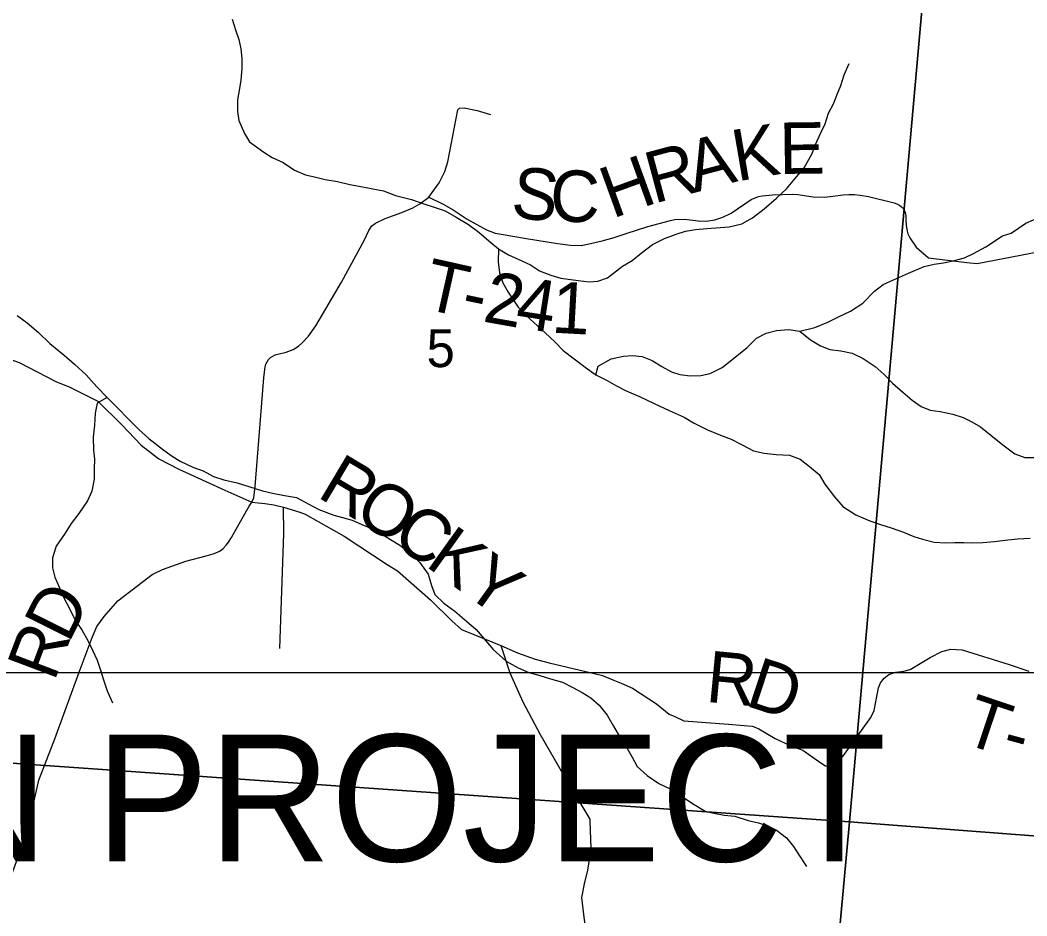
# Model space of a CAD drawing. Extents: x 0 to 34, y 0 to 22.
# Drawn here: x 6.672 to 7.784, y 17.231 to 18.22 of the extents above; entities that cross this region are included whole.
import ezdxf

# ---------------------------------------------------------------- set-up
doc = ezdxf.new("R2010")
doc.units = 0
for name, color, linetype in [('GM_X_Corporation', 7, 'Continuous'), ('GM_X_County_Road', 7, 'Continuous'), ('GM_X_County_Road_Text', 7, 'Continuous'), ('GM_X_Minor_River', 7, 'Continuous'), ('GM_X_Section_Text', 7, 'Continuous'), ('GM_X_Township_Road', 7, 'Continuous'), ('GM_X_Township_Road_Text', 7, 'Continuous'), ('SH_Data', 7, 'Continuous'), ('SH_Text', 7, 'Continuous')]:
    doc.layers.add(name, color=color, linetype=linetype)

msp = doc.modelspace()

# ---------------------------------------------------------------- linework, layer by layer
at = {"layer": 'GM_X_Corporation'}
for points in [[(6.6744, 18.4075), (7.6778, 18.3345), (7.5885, 17.3345), (6.5737, 17.4057)], [(7.6778, 18.3345), (8.6957, 18.2606), (8.5882, 17.2585), (7.5885, 17.3345)], [(6.5737, 17.4057), (7.5885, 17.3345), (7.4964, 16.3324), (6.463, 16.4089)], [(7.5885, 17.3345), (8.5882, 17.2585), (8.4813, 16.2644), (7.4964, 16.3324)]]:
    msp.add_lwpolyline(points, close=True, dxfattribs=at)
at = {"layer": 'GM_X_County_Road'}
msp.add_line((6.7375, 17.4998), (6.7375, 17.4998), dxfattribs=at)
for points in [[(6.2118, 17.9588), (6.2321, 17.9588), (6.2643, 17.95), (6.3295, 17.9354), (6.4064, 17.9208), (6.4599, 17.9101), (6.4852, 17.9043), (6.5222, 17.8926), (6.6078, 17.8644), (6.6711, 17.842), (6.7117, 17.8211), (6.7272, 17.8149), (6.7579, 17.7992), (6.7847, 17.773), (6.8061, 17.7506), (6.8254, 17.7355), (6.8475, 17.7243), (6.8983, 17.7008), (6.9283, 17.6876)], [(6.6455, 17.2305), (6.6736, 17.3056), (6.6834, 17.3382), (6.6929, 17.3807), (6.7105, 17.4262), (6.7375, 17.4998), (6.7519, 17.5381), (6.757, 17.5502), (6.7651, 17.5615), (6.7801, 17.5789), (6.818, 17.6079), (6.8295, 17.6135), (6.8554, 17.6224), (6.8779, 17.6283), (6.8856, 17.6306), (6.8903, 17.6324), (6.8933, 17.634), (6.8966, 17.6365), (6.9, 17.6401), (6.9026, 17.6437), (6.9056, 17.6488), (6.9176, 17.6697), (6.9253, 17.6832), (6.9283, 17.6876)]]:
    msp.add_lwpolyline(points, dxfattribs=at)
at = {"layer": 'GM_X_Minor_River'}
for p, q in [((6.7607, 17.5033), (6.762, 17.4995)), ((7.2226, 17.5048), (7.2343, 17.4995)), ((7.2343, 17.4995), (7.2343, 17.4995))]:
    msp.add_line(p, q, dxfattribs=at)
for points in [[(6.9066, 18.2213), (6.91, 18.2095), (6.9138, 18.1989), (6.9161, 18.1886), (6.9172, 18.178), (6.9172, 18.1666), (6.916, 18.154), (6.9145, 18.1445), (6.9122, 18.132), (6.9122, 18.1191), (6.9137, 18.1092), (6.9201, 18.0951), (6.9258, 18.0856), (6.9413, 18.0742), (6.9508, 18.0685), (6.963, 18.0631), (6.9755, 18.0544), (6.9876, 18.0494), (6.999, 18.0467), (7.0093, 18.0441), (7.0229, 18.0418), (7.0366, 18.0387), (7.0469, 18.0368), (7.0601, 18.0341), (7.0738, 18.0318), (7.0871, 18.0264), (7.1046, 18.0222), (7.1182, 18.0173), (7.1296, 18.0135), (7.1418, 18.0096), (7.1539, 18.0024), (7.1676, 17.9944), (7.1789, 17.986), (7.1899, 17.9765), (7.2006, 17.9674), (7.2119, 17.9609), (7.2264, 17.9544), (7.2359, 17.9498), (7.2461, 17.9433), (7.2586, 17.9384), (7.2696, 17.9353), (7.2886, 17.9326), (7.3012, 17.9311), (7.3106, 17.9318), (7.3213, 17.9356), (7.3376, 17.9485), (7.3483, 17.9546), (7.3582, 17.9629), (7.3707, 17.9724), (7.384, 17.9788), (7.3969, 17.9838), (7.4072, 17.9872), (7.4182, 17.989), (7.4308, 17.9902), (7.441, 17.9909), (7.4555, 17.992), (7.4695, 17.995), (7.4813, 18.0019), (7.4942, 18.0117), (7.5079, 18.0235), (7.519, 18.0337), (7.53, 18.047), (7.5384, 18.0569), (7.5471, 18.0728), (7.5509, 18.0827), (7.557, 18.0956), (7.5616, 18.1058), (7.5654, 18.1176), (7.5708, 18.1279)], [(7.5708, 18.1279), (7.5746, 18.1374), (7.5788, 18.148), (7.5826, 18.1598), (7.5883, 18.1723)], [(7.3082, 17.8285), (7.3109, 17.838), (7.3253, 17.8459), (7.339, 17.8489), (7.3489, 17.8497), (7.3595, 17.8485), (7.3705, 17.8443), (7.3811, 17.8375), (7.3918, 17.8318), (7.4012, 17.8287), (7.4126, 17.8272), (7.4244, 17.8275), (7.4347, 17.8298), (7.448, 17.8366), (7.4605, 17.8465), (7.4754, 17.8586), (7.4856, 17.8688), (7.4963, 17.8745), (7.5077, 17.8775), (7.5213, 17.8783), (7.5335, 17.8767), (7.5502, 17.8805), (7.5647, 17.8866), (7.5764, 17.8926), (7.5897, 17.8987), (7.6031, 17.9074), (7.616, 17.9207), (7.6259, 17.9283), (7.6373, 17.9332), (7.6536, 17.9408), (7.6711, 17.948), (7.6821, 17.9506), (7.6924, 17.9521), (7.703, 17.9544), (7.7156, 17.9578), (7.7254, 17.9623), (7.7391, 17.9699), (7.7574, 17.982), (7.7673, 17.985), (7.7832, 17.996), (7.8003, 18.0032)], [(7.2006, 17.9674), (7.2002, 17.9533), (7.202, 17.9411), (7.2054, 17.9301), (7.2115, 17.9198), (7.2225, 17.9031), (7.2358, 17.8898), (7.2521, 17.8753), (7.2634, 17.8646), (7.2722, 17.8551), (7.2964, 17.8369), (7.3082, 17.8285), (7.3207, 17.822), (7.331, 17.8163), (7.3416, 17.8106), (7.3564, 17.8045), (7.3727, 17.7968), (7.3894, 17.7888), (7.4057, 17.7816), (7.4163, 17.7755), (7.4315, 17.7678), (7.4459, 17.7617), (7.4577, 17.7572), (7.4691, 17.7514), (7.4824, 17.7446), (7.4942, 17.7419), (7.5074, 17.7404), (7.5223, 17.7396), (7.534, 17.7354), (7.5443, 17.727), (7.5549, 17.7182), (7.5613, 17.7076), (7.5719, 17.6935), (7.581, 17.6829), (7.5954, 17.6737), (7.611, 17.6672), (7.6228, 17.663), (7.6345, 17.6592), (7.6482, 17.6546), (7.6596, 17.6497), (7.6691, 17.647), (7.682, 17.6435), (7.6949, 17.6428), (7.7048, 17.6431), (7.7147, 17.6431), (7.7249, 17.6427), (7.7359, 17.6431), (7.7488, 17.6442), (7.7633, 17.6461), (7.7743, 17.6472), (7.7883, 17.6479)], [(6.6691, 17.8938), (6.6801, 17.8858), (6.6926, 17.8751), (6.7051, 17.8629), (6.7207, 17.85), (6.7324, 17.8401), (6.7453, 17.8283), (6.7571, 17.815), (6.7684, 17.8032), (6.8033, 17.7681), (6.8143, 17.7582), (6.8295, 17.7461), (6.839, 17.7392), (6.8492, 17.7331), (6.8629, 17.7262), (6.8743, 17.7224), (6.886, 17.7159), (6.8974, 17.7125), (6.9119, 17.7091), (6.9248, 17.7052), (6.9399, 17.7003), (6.951, 17.6976), (6.9642, 17.6949), (6.9775, 17.693), (6.9912, 17.6854), (7.0022, 17.6796), (7.0189, 17.6735), (7.0284, 17.6709), (7.039, 17.6678), (7.0496, 17.6632), (7.0603, 17.6586), (7.072, 17.6525), (7.0815, 17.6464), (7.0918, 17.6403), (7.1047, 17.6308), (7.1134, 17.6213), (7.1229, 17.608), (7.1266, 17.5958), (7.1304, 17.5856), (7.1403, 17.576), (7.1524, 17.5673), (7.1653, 17.5562), (7.1759, 17.5471), (7.1846, 17.5372), (7.1949, 17.525), (7.2093, 17.5121), (7.2226, 17.5048), (7.2343, 17.4995), (7.2465, 17.4964), (7.2583, 17.4926), (7.2715, 17.4888), (7.2829, 17.4831), (7.2932, 17.4774), (7.3027, 17.4717), (7.3121, 17.4633), (7.3209, 17.4526), (7.3277, 17.4404)], [(7.5335, 17.8767), (7.5453, 17.8672), (7.5563, 17.8604), (7.5669, 17.8565), (7.579, 17.855), (7.5916, 17.8523), (7.6037, 17.8466), (7.617, 17.8375), (7.6269, 17.8287), (7.6359, 17.8192), (7.6473, 17.8093), (7.6576, 17.8005), (7.6678, 17.7933), (7.6777, 17.7895), (7.6887, 17.7879), (7.7027, 17.7849), (7.7141, 17.7811), (7.7236, 17.7765), (7.7331, 17.7711), (7.7445, 17.7616), (7.7578, 17.751), (7.771, 17.7411), (7.7824, 17.7372), (7.7965, 17.7372)], [(6.7684, 17.8032), (6.7574, 17.7971), (6.7551, 17.7861), (6.7543, 17.7728), (6.7528, 17.7595), (6.7532, 17.745), (6.7543, 17.7352), (6.7539, 17.7245), (6.7539, 17.7131), (6.7516, 17.6998), (6.7466, 17.6892), (6.7371, 17.6752), (6.7287, 17.6641), (6.7219, 17.6535), (6.712, 17.6391), (6.7078, 17.6262), (6.7081, 17.6152), (6.7104, 17.6049), (6.721, 17.5813), (6.7267, 17.5703), (6.7335, 17.5566), (6.7403, 17.5467), (6.7475, 17.5342), (6.7524, 17.5235), (6.7573, 17.5132), (6.7607, 17.5033), (6.7641, 17.4927), (6.7683, 17.4794), (6.7743, 17.4661)], [(7.3277, 17.4404), (7.3345, 17.429), (7.3409, 17.4188), (7.3485, 17.4062), (7.3538, 17.3956), (7.3648, 17.3857), (7.3777, 17.3769), (7.391, 17.3708), (7.405, 17.3613), (7.4168, 17.3537), (7.4289, 17.3464), (7.4388, 17.3441), (7.4502, 17.3418), (7.462, 17.3407), (7.4764, 17.3361), (7.4878, 17.3334), (7.498, 17.33), (7.5079, 17.3254), (7.5189, 17.317), (7.5268, 17.3075), (7.5325, 17.298), (7.5409, 17.2851)]]:
    msp.add_lwpolyline(points, dxfattribs=at)
at = {"layer": 'GM_X_Township_Road'}
for p, q in [((7.2134, 17.4991), (7.2134, 17.4991)), ((7.2972, 17.5007), (7.3021, 17.4995)), ((7.6383, 17.4995), (7.6398, 17.5)), ((7.6398, 17.5), (7.6486, 17.5009)), ((7.6486, 17.5009), (7.6555, 17.5027))]:
    msp.add_line(p, q, dxfattribs=at)
for points in [[(7.1238, 18.0248), (7.1294, 18.0325), (7.1352, 18.0406), (7.1379, 18.0456), (7.1414, 18.0531), (7.1448, 18.0638), (7.1557, 18.1211), (7.1576, 18.1229), (7.1629, 18.1232), (7.177, 18.1204), (7.1919, 18.1159)], [(7.6652, 17.9667), (7.6759, 17.9575), (7.6789, 17.9572), (7.7183, 17.9525), (7.7297, 17.9515), (7.8943, 17.983), (7.9266, 17.9983), (7.948, 18.0062), (8.0137, 18.0356), (8.0309, 18.0433), (8.0483, 18.0551), (8.0653, 18.0717)], [(6.9283, 17.6876), (6.9304, 17.6926), (6.9318, 17.7051), (6.9414, 17.825), (6.9428, 17.8371), (6.9437, 17.84), (6.9467, 17.8453), (6.9487, 17.8474), (6.9539, 17.8503), (6.9568, 17.8513), (6.966, 17.8535), (6.974, 17.8564), (6.9797, 17.86), (6.9843, 17.864), (6.9907, 17.871), (6.9989, 17.8824), (7.0272, 17.9306), (7.0527, 17.9775), (7.0574, 17.9878), (7.0609, 17.9928), (7.065, 17.996), (7.0755, 18.001), (7.094, 18.0076), (7.1062, 18.0127), (7.1137, 18.0172), (7.1238, 18.0248), (7.1395, 18.0168), (7.1505, 18.0108), (7.1661, 18.0005), (7.1876, 17.9884), (7.1969, 17.985), (7.2036, 17.9836), (7.2316, 17.979), (7.2659, 17.9735), (7.2801, 17.9717), (7.2924, 17.9714), (7.3152, 17.9763), (7.3287, 17.98), (7.3419, 17.9846), (7.3657, 17.9921), (7.3906, 17.999), (7.3956, 18.0001), (7.4063, 18.0002), (7.4213, 17.9986), (7.4305, 17.9983), (7.4397, 17.9997), (7.4487, 18.0024), (7.4577, 18.0068), (7.4797, 18.0219), (7.4878, 18.0252), (7.4922, 18.0262), (7.5036, 18.0273), (7.5258, 18.0281), (7.5314, 18.0277), (7.5484, 18.0251), (7.5608, 18.0248), (7.57, 18.0258), (7.5817, 18.0272), (7.5878, 18.0276), (7.594, 18.0276), (7.6002, 18.027), (7.6095, 18.0254), (7.6378, 18.0182), (7.6408, 18.0174), (7.6437, 18.0159), (7.6459, 18.0141), (7.6478, 18.0122), (7.649, 18.0101), (7.65, 18.0077), (7.6506, 18.0041), (7.6509, 17.9997), (7.6513, 17.9933), (7.6522, 17.987), (7.6531, 17.9841), (7.6543, 17.9812), (7.656, 17.9786), (7.6622, 17.9694), (7.6652, 17.9667)], [(6.9283, 17.6876), (6.9352, 17.6869), (6.9425, 17.6862), (6.9526, 17.6846), (6.9631, 17.6822), (6.9812, 17.6768), (6.987, 17.6744), (7.0303, 17.6503), (7.0777, 17.6187), (7.0893, 17.612), (7.1255, 17.58), (7.149, 17.5567), (7.1598, 17.547), (7.1734, 17.5414), (7.2033, 17.5295), (7.2216, 17.5213), (7.2412, 17.5144), (7.2567, 17.5103), (7.2972, 17.5007), (7.3158, 17.4961), (7.329, 17.4909), (7.3361, 17.4877), (7.3489, 17.4821), (7.3752, 17.4648), (7.3894, 17.4535), (7.3954, 17.4511), (7.4056, 17.4463), (7.4549, 17.4426), (7.472, 17.4411), (7.4815, 17.4402), (7.4883, 17.4374), (7.5063, 17.4267), (7.5236, 17.4187), (7.5368, 17.4139), (7.5548, 17.4014), (7.5619, 17.3966), (7.5665, 17.3962), (7.5696, 17.3971), (7.5738, 17.3983), (7.5812, 17.4069), (7.6121, 17.45), (7.6157, 17.4575), (7.6204, 17.4825), (7.6228, 17.4882), (7.6267, 17.4934), (7.6318, 17.4975), (7.6398, 17.5), (7.6486, 17.5009), (7.6555, 17.5027), (7.6778, 17.5163), (7.6905, 17.5229), (7.7004, 17.5253), (7.713, 17.5247), (7.7651, 17.5084), (7.7866, 17.5011)], [(6.9593, 17.5261), (6.9634, 17.6532), (6.9631, 17.6822)], [(7.2033, 17.5295), (7.2134, 17.4991), (7.2277, 17.4672), (7.2466, 17.4311), (7.2783, 17.3763), (7.3016, 17.3375), (7.3017, 17.3355)], [(7.3017, 17.3355), (7.3027, 17.3056), (7.2992, 17.2809), (7.2958, 17.268), (7.2923, 17.2509), (7.2945, 17.2323), (7.2997, 17.1932)]]:
    msp.add_lwpolyline(points, dxfattribs=at)
at = {"layer": 'SH_Data'}
msp.add_line((6.0621, 17.4995), (7.9543, 17.4995), dxfattribs=at)

# ---------------------------------------------------------------- texts
at = {"layer": 'GM_X_County_Road_Text'}
for s, rotation, p in [('D', 63.3584, (6.7257, 17.5307)), ('R', 69.3133, (6.7098, 17.4885))]:
    msp.add_text(s, height=0.0568, rotation=rotation, dxfattribs=at).set_placement(p)
at = {"layer": 'GM_X_Section_Text'}
msp.add_text('5', height=0.0419, rotation=0, dxfattribs=at).set_placement((7.1213, 17.8369))
at = {"layer": 'GM_X_Township_Road_Text'}
for s, rotation, p in [('E', 0.7157, (7.5111, 18.0502)), ('K', 9.7624, (7.4642, 18.0419)), ('A', 14.88, (7.4172, 18.0294)), ('R', 15.0264, (7.3722, 18.0173)), ('H', 19.9103, (7.3264, 18.0006)), ('S', 353.2327, (7.2132, 18.0029)), ('C', 358.7743, (7.2573, 17.9979)), ('T', 347.3973, (7.1151, 17.9021)), ('2', 349.884, (7.1821, 17.8875)), ('4', 351.1475, (7.2179, 17.8812)), ('1', 356.8077, (7.2585, 17.8751)), ('-', 348.1103, (7.1574, 17.8927)), ('R', 329.235, (6.9989, 17.6943)), ('O', 327.4992, (7.0386, 17.6707)), ('C', 325.6929, (7.0803, 17.6441)), ('K', 324.4052, (7.1186, 17.618)), ('Y', 324.2798, (7.1593, 17.5889)), ('R', 354.5667, (7.4287, 17.4673)), ('D', 341.8104, (7.4719, 17.4635)), ('T', 341.4553, (7.7109, 17.4225)), ('-', 344.6455, (7.7545, 17.4079))]:
    msp.add_text(s, height=0.0568, rotation=rotation, dxfattribs=at).set_placement(p)
at = {"layer": 'SH_Text'}
msp.add_text('BEGIN PROJECT', height=0.14, dxfattribs=at).set_placement((6.1209, 17.2909))

doc.saveas('drawing.dxf')
